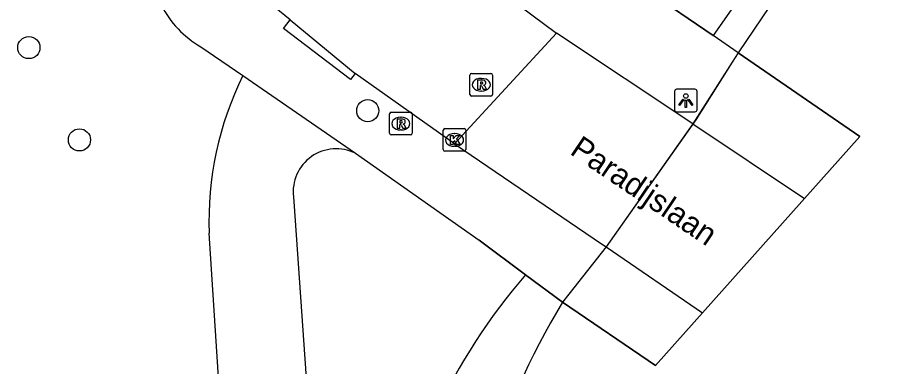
# Model space of a CAD drawing. Extents: x 160664 to 161506, y 382245 to 383288.
# Drawn here: x 161384.57 to 161423.79, y 382688.13 to 382703.5 of the extents above; entities that cross this region are included whole.
import ezdxf

# ---------------------------------------------------------------- set-up
doc = ezdxf.new("R2010")
doc.units = 0
for name, color, linetype in [('IMGEO_Boom', 7, 'Continuous'), ('IMGEO_Dek', 7, 'Continuous'), ('IMGEO_Erf', 7, 'Continuous'), ('IMGEO_Groenvoorziening', 7, 'Continuous'), ('IMGEO_Hek', 7, 'Continuous'), ('IMGEO_Kolk', 7, 'Continuous'), ('IMGEO_Lichtpunt', 7, 'Continuous'), ('IMGEO_Openbare_ruimte_label', 7, 'Continuous'), ('IMGEO_Rijbaan_lokaal_gesloten', 7, 'Continuous'), ('IMGEO_Rijbaan_lokaal_open', 7, 'Continuous'), ('IMGEO_Rioolput', 7, 'Continuous'), ('IMGEO_Voetpad_open', 7, 'Continuous'), ('IMGEO_Waterloop', 7, 'Continuous')]:
    doc.layers.add(name, color=color, linetype=linetype)

msp = doc.modelspace()

# ---------------------------------------------------------------- linework, layer by layer
at = {"layer": 'IMGEO_Boom'}
for centre in [(161385.06, 382702.19), (161400.02, 382699.404), (161387.294, 382698.118)]:
    msp.add_circle(centre, 0.489, dxfattribs=at)
at = {"layer": 'IMGEO_Dek'}
msp.add_lwpolyline([(161412.72, 382688.169), (161421.74, 382698.265), (161416.372, 382701.953), (161416.11, 382701.54), (161414.504, 382699.007), (161410.536, 382693.404), (161408.902, 382691.315), (161408.623, 382690.957), (161412.72, 382688.169)], close=True, dxfattribs=at)
at = {"layer": 'IMGEO_Erf'}
msp.add_arc((161426.933, 382674.911), 26.376, 139.1336, 155.1276, dxfattribs=at)
at = {"layer": 'IMGEO_Groenvoorziening'}
msp.add_lwpolyline([(161425.767, 382717.7), (161415.26, 382702.717)], dxfattribs=at)
at = {"layer": 'IMGEO_Hek'}
for points in [[(161412.365, 382704.706), (161415.26, 382702.717)], [(161416.372, 382701.953), (161415.26, 382702.717)], [(161416.372, 382701.953), (161421.74, 382698.265)], [(161406.987, 382692.169), (161404.938, 382693.687)], [(161408.623, 382690.957), (161406.987, 382692.169)], [(161412.72, 382688.169), (161408.623, 382690.957)], [(161412.72, 382688.169), (161412.72, 382688.169)]]:
    msp.add_lwpolyline(points, dxfattribs=at)
at = {"layer": 'IMGEO_Kolk'}
for p, q in [((161403.351, 382697.689), (161403.351, 382698.541)), ((161403.426, 382698.615), (161404.278, 382698.615)), ((161404.352, 382698.541), (161404.352, 382697.689)), ((161403.839, 382698.395), (161403.864, 382698.395)), ((161403.862, 382697.835), (161403.837, 382697.835)), ((161404.278, 382697.615), (161403.426, 382697.615))]:
    msp.add_line(p, q, dxfattribs=at)
for points in [[(161403.351, 382697.689), (161403.351, 382698.541)], [(161403.426, 382698.615), (161404.278, 382698.615)], [(161404.352, 382698.541), (161404.352, 382697.689)], [(161403.672, 382698.315), (161403.795, 382698.315), (161403.795, 382698.164), (161403.925, 382698.315), (161404.089, 382698.315), (161403.943, 382698.164), (161404.096, 382697.915), (161403.944, 382697.915), (161403.859, 382698.079), (161403.795, 382698.012), (161403.795, 382697.915), (161403.672, 382697.915), (161403.672, 382698.315)], [(161404.278, 382697.615), (161403.426, 382697.615)]]:
    msp.add_lwpolyline(points, dxfattribs=at)
for centre, start, end in [((161403.428, 382698.539), 91.552, 178.448), ((161403.428, 382698.539), 91.552, 178.448), ((161404.276, 382698.539), 1.552, 88.448), ((161404.276, 382698.539), 1.552, 88.448), ((161403.428, 382697.691), 181.552, 268.448), ((161403.428, 382697.691), 181.552, 268.448), ((161404.276, 382697.691), 271.552, 358.448), ((161404.276, 382697.691), 271.552, 358.448)]:
    msp.add_arc(centre, 0.0765, start, end, dxfattribs=at)
for centre, major_axis, ratio, start_param, end_param in [((161403.838, 382698.115), (-0.387, 0.002), 0.722429, 4.712389, 7.853982), ((161403.863, 382698.115), (-0.39, 0.002), 0.717154, 1.570796, 4.712389)]:
    msp.add_ellipse(centre, major_axis=major_axis, ratio=ratio, start_param=start_param, end_param=end_param, dxfattribs=at)
at = {"layer": 'IMGEO_Lichtpunt'}
for p, q in [((161413.561, 382700.256), (161413.561, 382699.449)), ((161413.561, 382700.256), (161413.561, 382699.449)), ((161414.463, 382700.351), (161413.655, 382700.351)), ((161414.463, 382700.351), (161413.655, 382700.351)), ((161414.557, 382699.449), (161414.557, 382700.256)), ((161414.557, 382699.449), (161414.557, 382700.256)), ((161413.655, 382699.355), (161414.463, 382699.355)), ((161413.655, 382699.355), (161414.463, 382699.355))]:
    msp.add_line(p, q, dxfattribs=at)
for points in [[(161413.935, 382699.92), (161413.974, 382699.892), (161413.786, 382699.63), (161413.748, 382699.657), (161413.935, 382699.92)], [(161414.037, 382699.872), (161414.084, 382699.872), (161414.084, 382699.55), (161414.037, 382699.55), (161414.037, 382699.872)], [(161414.147, 382699.892), (161414.185, 382699.919), (161414.372, 382699.657), (161414.333, 382699.629), (161414.147, 382699.892)]]:
    msp.add_lwpolyline(points, dxfattribs=at)
msp.add_circle((161414.06, 382700.054), 0.0994, dxfattribs=at)
for centre, start, end in [((161413.655, 382700.256), 90, 180), ((161413.655, 382700.256), 90, 180), ((161414.463, 382700.256), 0, 90), ((161414.463, 382700.256), 0, 90), ((161413.655, 382699.449), 180, 270), ((161413.655, 382699.449), 180, 270), ((161414.463, 382699.449), 270, 0), ((161414.463, 382699.449), 270, 360)]:
    msp.add_arc(centre, 0.0946, start, end, dxfattribs=at)
at = {"layer": 'IMGEO_Rijbaan_lokaal_gesloten'}
for points in [[(161414.37, 382698.818), (161419.299, 382695.533)], [(161410.536, 382693.404), (161414.794, 382690.491), (161414.794, 382690.491)]]:
    msp.add_lwpolyline(points, dxfattribs=at)
at = {"layer": 'IMGEO_Rijbaan_lokaal_open'}
for points in [[(161396.594, 382703.406), (161395.105, 382704.634), (161392.435, 382707.001)], [(161406.179, 382704.457), (161408.358, 382702.826)], [(161396.594, 382703.406), (161399.459, 382701.043)], [(161408.358, 382702.826), (161403.845, 382697.944)], [(161414.37, 382698.818), (161408.358, 382702.826)], [(161403.845, 382697.944), (161399.459, 382701.043)], [(161414.37, 382698.818), (161410.536, 382693.404)], [(161403.845, 382697.944), (161410.383, 382693.509), (161410.536, 382693.404)]]:
    msp.add_lwpolyline(points, dxfattribs=at)
at = {"layer": 'IMGEO_Rioolput'}
for p, q in [((161404.531, 382700.122), (161404.531, 382700.974)), ((161404.606, 382701.048), (161405.458, 382701.048)), ((161405.532, 382700.974), (161405.532, 382700.122)), ((161405.019, 382700.828), (161405.044, 382700.828)), ((161405.042, 382700.268), (161405.017, 382700.268)), ((161405.458, 382700.048), (161404.606, 382700.048)), ((161401.055, 382699.335), (161401.907, 382699.335)), ((161400.98, 382698.409), (161400.98, 382699.261)), ((161401.468, 382699.115), (161401.493, 382699.115)), ((161401.981, 382699.261), (161401.981, 382698.409)), ((161401.491, 382698.555), (161401.466, 382698.555)), ((161401.907, 382698.335), (161401.055, 382698.335))]:
    msp.add_line(p, q, dxfattribs=at)
for points in [[(161404.531, 382700.122), (161404.531, 382700.974)], [(161404.606, 382701.048), (161405.458, 382701.048)], [(161405.532, 382700.974), (161405.532, 382700.122)], [(161405.12, 382700.746), (161404.868, 382700.748), (161404.868, 382700.348)], [(161404.868, 382700.348), (161404.992, 382700.348), (161404.992, 382700.51), (161405.003, 382700.51)], [(161405.046, 382700.667), (161404.992, 382700.667), (161404.992, 382700.586)], [(161404.992, 382700.586), (161405.044, 382700.586)], [(161405.05, 382700.481), (161405.121, 382700.348), (161405.261, 382700.348), (161405.196, 382700.474)], [(161405.458, 382700.048), (161404.606, 382700.048)], [(161401.055, 382699.335), (161401.907, 382699.335)], [(161400.98, 382698.409), (161400.98, 382699.261)], [(161401.569, 382699.033), (161401.317, 382699.035), (161401.317, 382698.635)], [(161401.495, 382698.954), (161401.441, 382698.954), (161401.441, 382698.873)], [(161401.981, 382699.261), (161401.981, 382698.409)], [(161401.317, 382698.635), (161401.441, 382698.635), (161401.441, 382698.797), (161401.452, 382698.797)], [(161401.441, 382698.873), (161401.493, 382698.873)], [(161401.499, 382698.768), (161401.57, 382698.635), (161401.71, 382698.635), (161401.645, 382698.761)], [(161401.907, 382698.335), (161401.055, 382698.335)]]:
    msp.add_lwpolyline(points, dxfattribs=at)
for centre, radius, start, end in [((161404.608, 382700.972), 0.0765, 91.552, 178.448), ((161404.608, 382700.972), 0.0765, 91.552, 178.448), ((161405.456, 382700.972), 0.0765, 1.552, 88.448), ((161405.456, 382700.972), 0.0765, 1.552, 88.448), ((161405.002, 382700.457), 0.0533, 26.0293, 88.6989), ((161405.028, 382700.775), 0.19, 274.7715, 282.9687), ((161405.052, 382700.571), 0.0964, 77.0061, 93.1865), ((161405.066, 382700.628), 0.0378, 276.6634, 79.6772), ((161405.119, 382700.636), 0.109, 350.3612, 89.416), ((161405.117, 382700.636), 0.112, 277.5842, 350.9817), ((161405.101, 382700.421), 0.108, 29.5134, 73.7905), ((161404.608, 382700.124), 0.0765, 181.552, 268.448), ((161404.608, 382700.124), 0.0765, 181.552, 268.448), ((161405.456, 382700.124), 0.0765, 271.552, 358.448), ((161405.456, 382700.124), 0.0765, 271.552, 358.448), ((161401.057, 382699.259), 0.0765, 91.552, 178.448), ((161401.057, 382699.259), 0.0765, 91.552, 178.448), ((161401.905, 382699.259), 0.0765, 1.552, 88.448), ((161401.905, 382699.259), 0.0765, 1.552, 88.448), ((161401.501, 382698.858), 0.0964, 77.0061, 93.1865), ((161401.515, 382698.915), 0.0378, 276.6634, 79.6772), ((161401.568, 382698.923), 0.109, 350.3612, 89.416), ((161401.451, 382698.744), 0.0533, 26.0293, 88.6989), ((161401.477, 382699.062), 0.19, 274.7715, 282.9687), ((161401.566, 382698.923), 0.112, 277.5842, 350.9817), ((161401.55, 382698.708), 0.108, 29.5134, 73.7905), ((161401.057, 382698.411), 0.0765, 181.552, 268.448), ((161401.057, 382698.411), 0.0765, 181.552, 268.448), ((161401.905, 382698.411), 0.0765, 271.552, 358.448), ((161401.905, 382698.411), 0.0765, 271.552, 358.448)]:
    msp.add_arc(centre, radius, start, end, dxfattribs=at)
for centre, major_axis, ratio, start_param, end_param in [((161405.018, 382700.548), (-0.387, 0.002), 0.722429, 4.712389, 7.853982), ((161405.043, 382700.548), (-0.39, 0.002), 0.717154, 1.570796, 4.712389), ((161401.467, 382698.835), (-0.387, 0.002), 0.722429, 4.712389, 7.853982), ((161401.492, 382698.835), (-0.39, 0.002), 0.717154, 1.570796, 4.712389)]:
    msp.add_ellipse(centre, major_axis=major_axis, ratio=ratio, start_param=start_param, end_param=end_param, dxfattribs=at)
at = {"layer": 'IMGEO_Voetpad_open'}
for points in [[(161415.26, 382702.717), (161412.365, 382704.706), (161412.094, 382704.316), (161411.637, 382704.618)], [(161399.459, 382701.043), (161399.253, 382700.774), (161396.305, 382703.027), (161396.594, 382703.406)], [(161416.372, 382701.953), (161415.26, 382702.717)], [(161392.648, 382702.223), (161394.511, 382700.959)], [(161416.372, 382701.953), (161416.11, 382701.54), (161414.37, 382698.818)], [(161394.511, 382700.959), (161399.479, 382697.527)], [(161399.479, 382697.527), (161404.938, 382693.687), (161406.987, 382692.169)], [(161396.74, 382695.6), (161399.074, 382662.143), (161395.902, 382661.933), (161394.414, 382683.625), (161393.703, 382683.557), (161393.019, 382694.003)], [(161410.536, 382693.404), (161408.902, 382691.315), (161408.623, 382690.957)], [(161406.987, 382692.169), (161408.623, 382690.957)]]:
    msp.add_lwpolyline(points, dxfattribs=at)
for centre, radius, start, end in [((161394.885, 382706.084), 4.462, 206.9559, 239.9063), ((161407.423, 382694.552), 14.414, 153.6069, 182.1811), ((161398.632, 382695.821), 1.905, 63.5896, 186.6664)]:
    msp.add_arc(centre, radius, start, end, dxfattribs=at)
at = {"layer": 'IMGEO_Waterloop'}
msp.add_lwpolyline([(161423.998, 382713.232), (161416.372, 382701.953)], dxfattribs=at)
msp.add_arc((161437.232, 382673.577), 33.475, 148.722, 177.4459, dxfattribs=at)

# ---------------------------------------------------------------- texts
at = {"layer": 'IMGEO_Openbare_ruimte_label'}
msp.add_text('Paradijslaan', height=1, rotation=325.9605, dxfattribs=at).set_placement((161408.896, 382697.522))

doc.saveas('drawing.dxf')
